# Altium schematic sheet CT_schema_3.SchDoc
size 280 x 236 mm
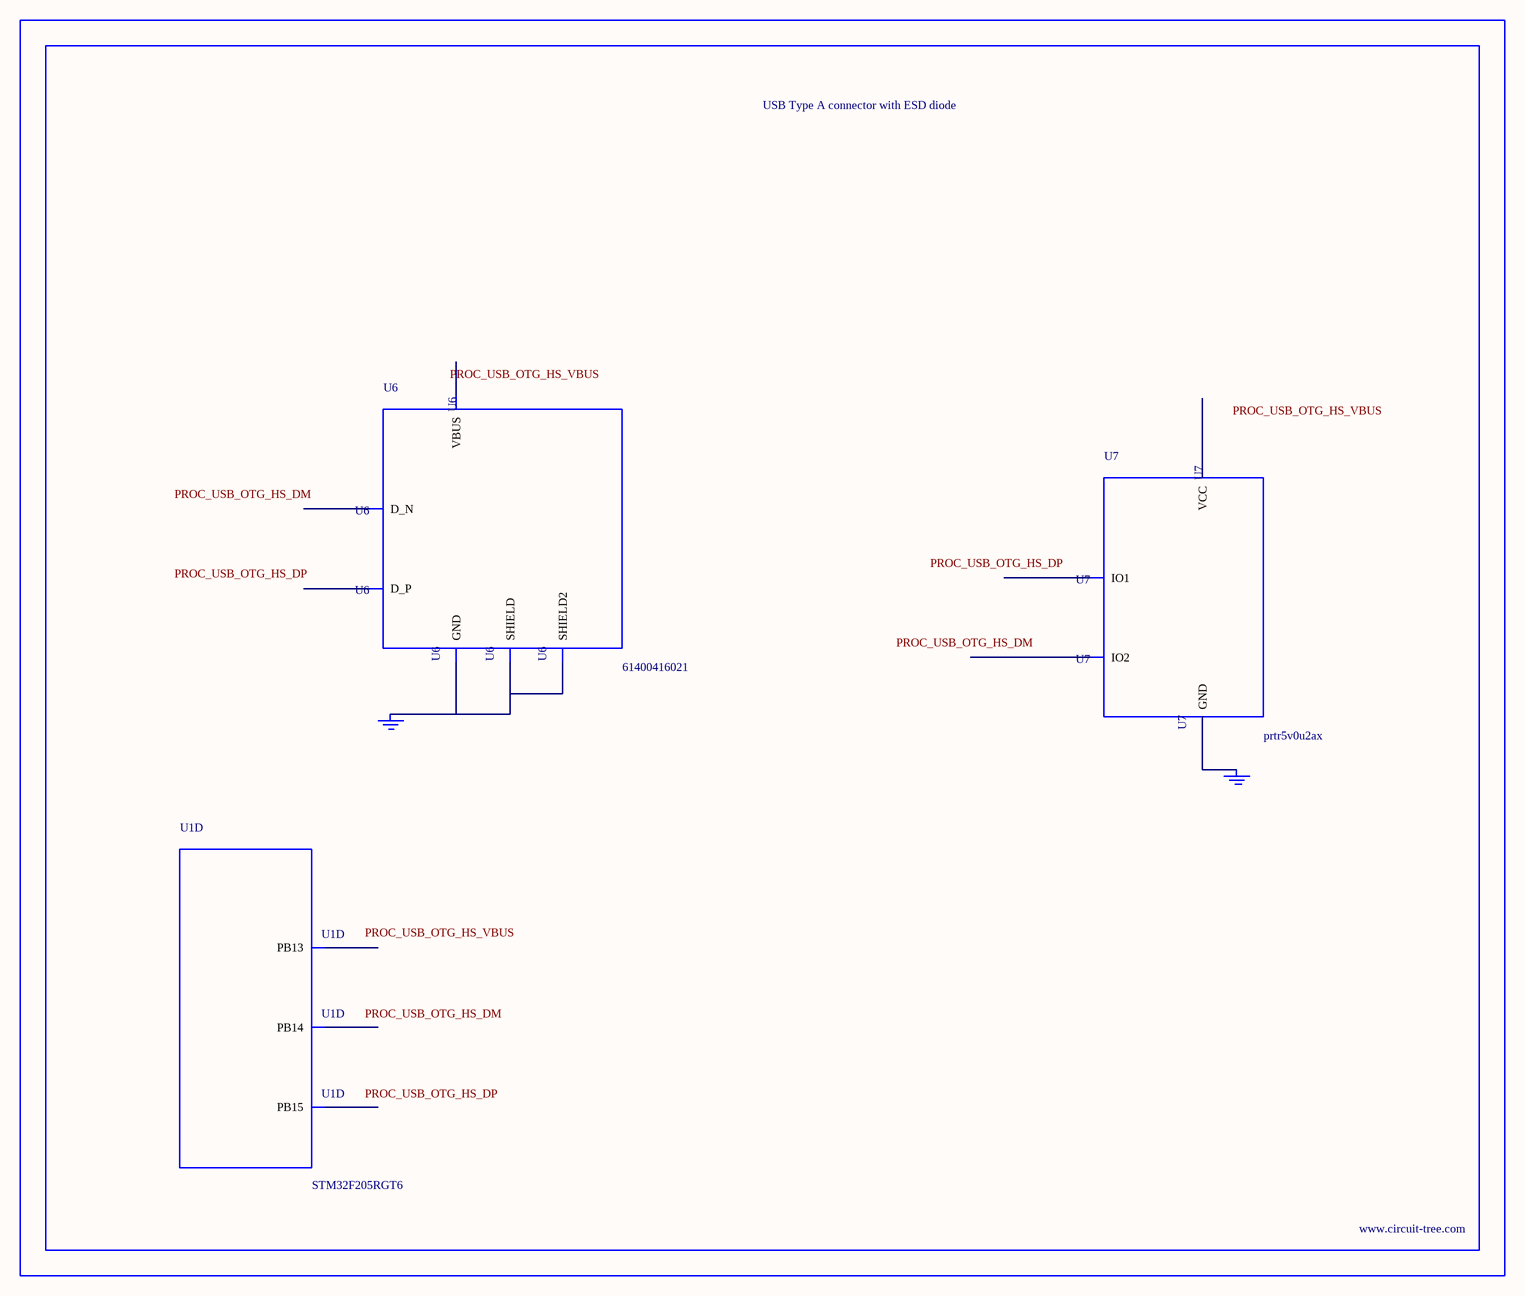
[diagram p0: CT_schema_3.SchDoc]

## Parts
BORDER2  (no value)
GND_INSTANCE_2_0  (no value)
GND_INSTANCE_2_1  (no value)
U1  STM32F205RGT6  [LQFP64]  (part D of 5)
U6  61400416021  [USB-A-H]
U7  prtr5v0u2ax  [SOT143B]

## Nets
NetGND_INSTANCE_2_0_0: GND_INSTANCE_2_0.0(GND) U6.4(GND) U6.5(SHIELD) U6.6(SHIELD2)
NetGND_INSTANCE_2_1_0: GND_INSTANCE_2_1.0(GND) U7.1(GND)

Not connected (* = marked no-connect by the designer): U1 34(PB13) 35(PB14) 36(PB15); U6 1(VBUS) 2(D_N) 3(D_P); U7 2(IO1) 3(IO2) 4(VCC)

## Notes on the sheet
- Labels drawn without touching a wire or pin: PROC_USB_OTG_HS_DM, PROC_USB_OTG_HS_DP, PROC_USB_OTG_HS_VBUS

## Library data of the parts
BORDER2 = BORDER_PAGE2
GND_INSTANCE_2_0 GND_INSTANCE_2_1 = GND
